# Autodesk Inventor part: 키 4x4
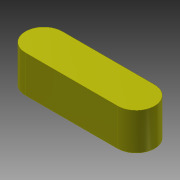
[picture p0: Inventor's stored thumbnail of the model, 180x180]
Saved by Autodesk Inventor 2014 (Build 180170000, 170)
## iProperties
Created: 2016-04
Part Number: 키 4x4
Document SubType Name: Modeling
Designer: mdu
Density: 7.86 g/cm^3
Mass: 1.59075 g
Surface Area: 2.15671 cm^2
Volume: 0.202386 cm^3
Material: 강철, 연강
Appearance: 노란색
Author: mdu
Revision Number: 1
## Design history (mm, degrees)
sketch "스케치1"
  geometry: L1 (-5, -2)-(5, -2); L2 (5, 2)-(-5, 2); A1 r 2 centre (5, 0) between (5, -2) and (5, 2); A2 r 2 centre (-5, 0) between (-5, 2) and (-5, -2); 2 further points
  constraints: 4 end point, 4 point on circle, 4 tangent, 2 centre point, 1 horizontal, 1 horizontal alignment, 1 midpoint, 1 parallel, 1 vertical alignment
  dimensions: "d0" = 4 distance between parallel lines of L1 L2; "d1" = 14 dimension on A1 A2
extrude "돌출1" new body sketch "스케치1" stored distance "d2" = 4; taper "d3" = 0 deg
chamfer "모따기1" distance "d4" = 0.5; stored, may be unused: second distance "d5" = 2, angle "d6" = 45 deg
node "솔리드1"
other parameters: "d0" = 4
